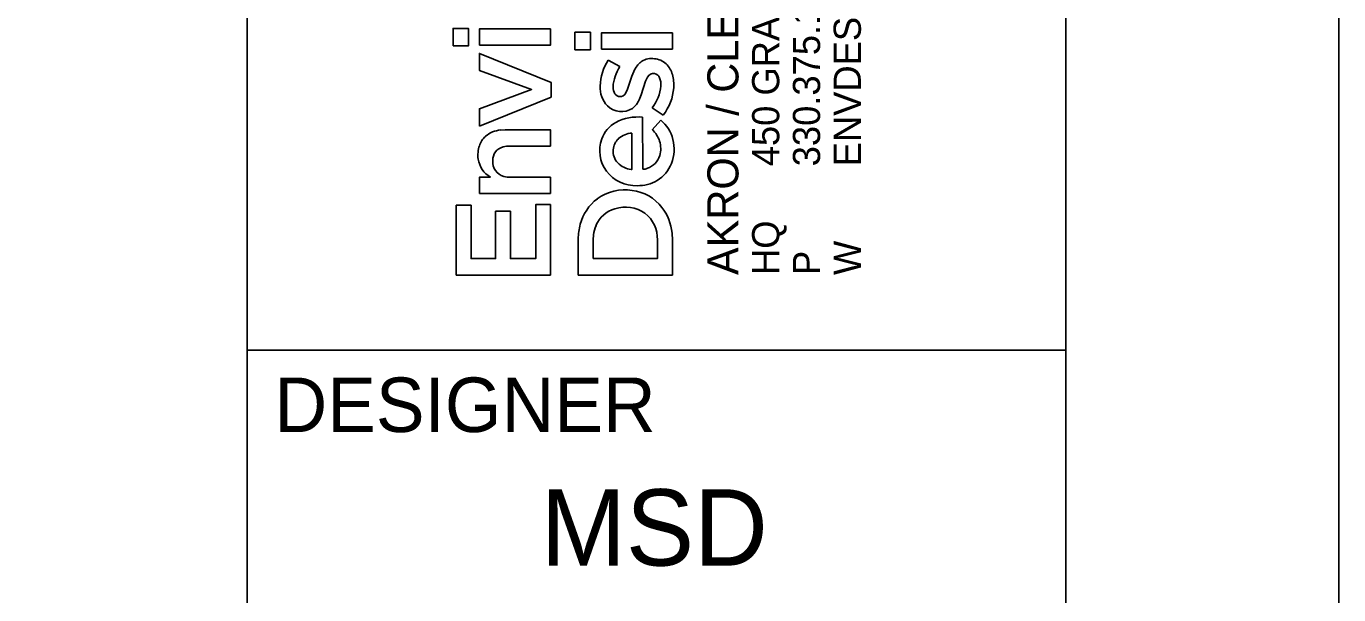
# Model space of a CAD drawing. Extents: x -4.5 to 34, y -0.4 to 22.
# Drawn here: x 31.595 to 34, y 2.552 to 3.594 of the extents above; entities that cross this region are included whole.
import ezdxf

# ---------------------------------------------------------------- set-up
doc = ezdxf.new("R2010")
doc.units = 0
for name, color, linetype in [('SH_Border', 7, 'Continuous'), ('SH_Cut_Line', 7, 'Continuous'), ('SH_Data', 7, 'Continuous')]:
    doc.layers.add(name, color=color, linetype=linetype)

msp = doc.modelspace()

# ---------------------------------------------------------------- linework, layer by layer
at = {"layer": 'SH_Border'}
for p, q in [((32, 0.5), (32, 21.5)), ((32, 3), (33.5, 3))]:
    msp.add_line(p, q, dxfattribs=at)
msp.add_lwpolyline([(1.5, 21.5), (33.5, 21.5), (33.5, 0.5), (1.5, 0.5)], close=True, dxfattribs=at)
at = {"layer": 'SH_Cut_Line'}
msp.add_lwpolyline([(0, 0), (34, 0), (34, 22), (0, 22)], close=True, dxfattribs=at)
at = {"layer": 'SH_Data'}
for p, q in [((32.3771, 3.5582), (32.3771, 3.5903)), ((32.3771, 3.5903), (32.4054, 3.5903)), ((32.4054, 3.5903), (32.4054, 3.5582)), ((32.4254, 3.5594), (32.4254, 3.5893)), ((32.4254, 3.5893), (32.5557, 3.5893)), ((32.5557, 3.5893), (32.5557, 3.5594)), ((32.5557, 3.5594), (32.4254, 3.5594)), ((32.6005, 3.5511), (32.6005, 3.5832)), ((32.6005, 3.5832), (32.6289, 3.5832)), ((32.6289, 3.5832), (32.6289, 3.5511)), ((32.6489, 3.5523), (32.6489, 3.5822)), ((32.6489, 3.5822), (32.7792, 3.5822)), ((32.7792, 3.5822), (32.7792, 3.5523)), ((32.4054, 3.5582), (32.3771, 3.5582)), ((32.4254, 3.5133), (32.4254, 3.5446)), ((32.4254, 3.5446), (32.5567, 3.4913)), ((32.6289, 3.5511), (32.6005, 3.5511)), ((32.7792, 3.5523), (32.6489, 3.5523)), ((32.5212, 3.478), (32.4254, 3.5133)), ((32.6615, 3.5321), (32.6827, 3.5203)), ((32.7048, 3.5026), (32.7104, 3.5153)), ((32.5567, 3.4913), (32.5567, 3.4644)), ((32.6967, 3.4787), (32.7048, 3.5026)), ((32.7298, 3.4933), (32.7221, 3.4688)), ((32.7334, 3.501), (32.7298, 3.4933)), ((32.4254, 3.4429), (32.5212, 3.478)), ((32.5567, 3.4644), (32.4254, 3.4109)), ((32.693, 3.4712), (32.6967, 3.4787)), ((32.7221, 3.4688), (32.7182, 3.4592)), ((32.4254, 3.4109), (32.4254, 3.4429)), ((32.7621, 3.4314), (32.742, 3.4447)), ((32.7245, 3.4275), (32.7246, 3.3319)), ((32.7423, 3.4046), (32.7577, 3.422)), ((32.4644, 3.404), (32.4729, 3.4044)), ((32.4729, 3.4044), (32.5557, 3.4044)), ((32.5557, 3.4044), (32.5557, 3.3746)), ((32.7049, 3.3318), (32.7049, 3.3983)), ((32.5557, 3.3746), (32.4814, 3.3746)), ((32.7036, 3.3317), (32.7049, 3.3318)), ((32.4254, 3.2875), (32.4254, 3.3173)), ((32.4254, 3.3173), (32.4455, 3.3173)), ((32.4822, 3.3173), (32.5557, 3.3173)), ((32.5557, 3.3173), (32.5557, 3.2876)), ((32.5557, 3.2876), (32.4254, 3.2875)), ((32.383, 3.1379), (32.383, 3.266)), ((32.383, 3.266), (32.4101, 3.266)), ((32.4101, 3.266), (32.4101, 3.1683)), ((32.455, 3.1683), (32.455, 3.2549)), ((32.455, 3.2549), (32.4822, 3.2549)), ((32.4822, 3.2549), (32.4822, 3.1683)), ((32.5286, 3.1683), (32.5286, 3.2672)), ((32.5286, 3.2672), (32.5557, 3.2672)), ((32.5557, 3.2672), (32.5557, 3.1379)), ((32.6064, 3.138), (32.6064, 3.204)), ((32.6347, 3.2118), (32.6341, 3.2023)), ((32.6341, 3.2023), (32.6341, 3.1684)), ((32.7515, 3.1683), (32.7515, 3.2024)), ((32.7785, 3.215), (32.7792, 3.2021)), ((32.7792, 3.2021), (32.7792, 3.138)), ((32.4101, 3.1683), (32.455, 3.1683)), ((32.4822, 3.1683), (32.5286, 3.1683)), ((32.6341, 3.1684), (32.7515, 3.1683)), ((32.5557, 3.1379), (32.383, 3.1379)), ((32.7792, 3.138), (32.6064, 3.138))]:
    msp.add_line(p, q, dxfattribs=at)
for points in [[(32.3771, 3.5582), (32.3771, 3.5903), (32.4054, 3.5903), (32.4054, 3.5582)], [(32.4254, 3.5594), (32.4254, 3.5893), (32.5557, 3.5893), (32.5557, 3.5594)], [(32.6005, 3.5511), (32.6005, 3.5832), (32.6289, 3.5832), (32.6289, 3.5511)], [(32.6489, 3.5523), (32.6489, 3.5822), (32.7792, 3.5822), (32.7792, 3.5523)], [(32.4254, 3.4109), (32.4254, 3.4429), (32.5212, 3.478), (32.4254, 3.5133), (32.4254, 3.5446), (32.5567, 3.4913), (32.5567, 3.4644)], [(32.383, 3.1379), (32.383, 3.266), (32.4101, 3.266), (32.4101, 3.1683), (32.455, 3.1683), (32.455, 3.2549), (32.4822, 3.2549), (32.4822, 3.1683), (32.5286, 3.1683), (32.5286, 3.2672), (32.5557, 3.2672), (32.5557, 3.1379)]]:
    msp.add_lwpolyline(points, close=True, dxfattribs=at)
for points in [[(32.6615, 3.5321), (32.6827, 3.5203)], [(32.693, 3.4712), (32.6967, 3.4787), (32.7048, 3.5026), (32.7104, 3.5153)], [(32.7334, 3.501), (32.7298, 3.4933), (32.7221, 3.4688), (32.7182, 3.4592)], [(32.7621, 3.4314), (32.742, 3.4447)], [(32.7245, 3.4275), (32.7246, 3.3319)], [(32.7423, 3.4046), (32.7577, 3.422)], [(32.4644, 3.404), (32.4729, 3.4044), (32.5557, 3.4044), (32.5557, 3.3746), (32.4814, 3.3746)], [(32.7036, 3.3317), (32.7049, 3.3318), (32.7049, 3.3983)], [(32.4254, 3.2875), (32.4254, 3.3173), (32.4455, 3.3173)], [(32.4822, 3.3173), (32.5557, 3.3173), (32.5557, 3.2876), (32.4254, 3.2875)], [(32.7785, 3.215), (32.7792, 3.2021), (32.7792, 3.138), (32.6064, 3.138)], [(32.6064, 3.138), (32.6064, 3.204)], [(32.6347, 3.2118), (32.6341, 3.2023), (32.6341, 3.1684), (32.7515, 3.1683), (32.7515, 3.2024)]]:
    msp.add_lwpolyline(points, dxfattribs=at)
for centre, radius, start, end in [((32.7406, 3.5026), 0.0326, 80.1719, 122.5197), ((32.7406, 3.5026), 0.0326, 80.1719, 122.5197), ((32.7364, 3.4826), 0.0897, 146.531, 178.7571), ((32.7364, 3.4826), 0.0897, 146.531, 178.7571), ((32.7452, 3.4789), 0.0749, 146.5112, 176.9101), ((32.7452, 3.4789), 0.0749, 146.5112, 176.9101), ((32.7466, 3.4971), 0.0405, 125.5118, 153.4159), ((32.7466, 3.4971), 0.0405, 125.5118, 153.4159), ((32.7428, 3.4982), 0.0367, 47.7934, 84.6892), ((32.7428, 3.4982), 0.0367, 47.7934, 84.6892), ((32.7379, 3.4946), 0.0427, 14.9966, 46.2063), ((32.7379, 3.4946), 0.0427, 14.9966, 46.2063), ((32.7438, 3.4963), 0.0114, 76.6609, 155.7053), ((32.7438, 3.4963), 0.0114, 76.6609, 155.7053), ((32.744, 3.4951), 0.0126, 21.5098, 78.5262), ((32.744, 3.4951), 0.0126, 21.5098, 78.5262), ((32.7259, 3.4877), 0.0321, 354.5726, 22.068), ((32.7259, 3.4877), 0.0321, 354.5726, 22.068), ((32.7104, 3.4867), 0.0712, 355.8306, 15.3914), ((32.7104, 3.4867), 0.0712, 355.8306, 15.3914), ((32.6967, 3.4824), 0.0501, 177.5366, 222.7932), ((32.6967, 3.4824), 0.0501, 177.5366, 222.7932), ((32.6931, 3.4823), 0.0228, 178.4747, 211.0868), ((32.6931, 3.4823), 0.0228, 178.4747, 211.0868), ((32.6833, 3.4767), 0.0115, 212.2368, 268.3777), ((32.6833, 3.4767), 0.0115, 212.2368, 268.3777), ((32.6834, 3.4759), 0.0107, 267.716, 333.7337), ((32.6834, 3.4759), 0.0107, 267.716, 333.7337), ((32.6825, 3.4915), 0.0757, 321.811, 354.7969), ((32.6825, 3.4915), 0.0757, 321.811, 354.7969), ((32.6895, 3.4882), 0.0922, 321.9777, 355.8738), ((32.6895, 3.4882), 0.0922, 321.9777, 355.8738), ((32.686, 3.4753), 0.0375, 225.9854, 302.4797), ((32.686, 3.4753), 0.0375, 225.9854, 302.4797), ((32.681, 3.4758), 0.0408, 308.0877, 335.9874), ((32.681, 3.4758), 0.0408, 308.0877, 335.9874), ((32.7024, 3.3691), 0.0558, 118.8308, 160.6244), ((32.7024, 3.3691), 0.0558, 118.8308, 160.6244), ((32.7152, 3.3441), 0.0838, 83.615, 118.2876), ((32.7152, 3.3441), 0.0838, 83.615, 118.2876), ((32.7174, 3.3717), 0.0644, 13.5336, 51.3615), ((32.7174, 3.3717), 0.0644, 13.5336, 51.3615), ((32.4635, 3.3626), 0.0402, 132.2219, 161.6818), ((32.4635, 3.3626), 0.0402, 132.2219, 161.6818), ((32.4687, 3.3543), 0.0499, 94.9696, 130.2225), ((32.4687, 3.3543), 0.0499, 94.9696, 130.2225), ((32.7079, 3.3561), 0.0424, 94.008, 130.8817), ((32.7079, 3.3561), 0.0424, 94.008, 130.8817), ((32.7038, 3.3656), 0.0549, 19.0357, 45.4406), ((32.7038, 3.3656), 0.0549, 19.0357, 45.4406), ((32.4787, 3.3582), 0.056, 162.2736, 187.7919), ((32.4787, 3.3582), 0.056, 162.2736, 187.7919), ((32.4748, 3.3487), 0.025, 103.6865, 182.2187), ((32.4748, 3.3487), 0.025, 103.6865, 182.2187), ((32.4811, 3.3286), 0.046, 89.6049, 105.3284), ((32.4811, 3.3286), 0.046, 89.6049, 105.3284), ((32.7104, 3.3661), 0.0644, 160.5201, 215.7831), ((32.7104, 3.3661), 0.0644, 160.5201, 215.7831), ((32.7017, 3.365), 0.0311, 175.0013, 223.283), ((32.7017, 3.365), 0.0311, 175.0013, 223.283), ((32.7005, 3.3663), 0.0298, 132.9851, 177.179), ((32.7005, 3.3663), 0.0298, 132.9851, 177.179), ((32.7107, 3.3697), 0.047, 344.6059, 17.007), ((32.7107, 3.3697), 0.047, 344.6059, 17.007), ((32.7064, 3.3692), 0.0758, 339.3542, 13.3785), ((32.7064, 3.3692), 0.0758, 339.3542, 13.3785), ((32.4703, 3.358), 0.0476, 188.962, 238.7037), ((32.4703, 3.358), 0.0476, 188.962, 238.7037), ((32.4773, 3.3456), 0.0276, 175.5854, 255.1439), ((32.4773, 3.3456), 0.0276, 175.5854, 255.1439), ((32.7089, 3.3736), 0.0423, 225.0619, 262.7974), ((32.7089, 3.3736), 0.0423, 225.0619, 262.7974), ((32.7224, 3.3671), 0.035, 288.0077, 343.5508), ((32.7224, 3.3671), 0.035, 288.0077, 343.5508), ((32.4818, 3.3595), 0.0422, 254.0916, 270.5284), ((32.4818, 3.3595), 0.0422, 254.0916, 270.5284), ((32.7125, 3.3705), 0.0687, 217.7452, 271.6543), ((32.7125, 3.3705), 0.0687, 217.7452, 271.6543), ((32.7247, 3.3522), 0.0202, 269.7003, 294.8711), ((32.7247, 3.3522), 0.0202, 269.7003, 294.8711), ((32.7189, 3.3652), 0.0626, 300.9427, 338.7323), ((32.7189, 3.3652), 0.0626, 300.9427, 338.7323), ((32.7155, 3.3724), 0.0706, 269.2048, 300.3341), ((32.7155, 3.3724), 0.0706, 269.2048, 300.3341), ((32.6939, 3.2089), 0.0865, 127.2362, 165.148), ((32.6939, 3.2089), 0.0865, 127.2362, 165.148), ((32.6923, 3.2079), 0.0864, 81.194, 125.9984), ((32.6923, 3.2079), 0.0864, 81.194, 125.9984), ((32.6946, 3.2113), 0.0827, 37.8521, 82.402), ((32.6946, 3.2113), 0.0827, 37.8521, 82.402), ((32.6889, 3.2078), 0.054, 106.1881, 157.3861), ((32.6889, 3.2078), 0.054, 106.1881, 157.3861), ((32.6928, 3.1986), 0.0639, 55.6727, 107.2093), ((32.6928, 3.1986), 0.0639, 55.6727, 107.2093), ((32.6929, 3.205), 0.0587, 357.4662, 52.2665), ((32.6929, 3.205), 0.0587, 357.4662, 52.2665), ((32.6859, 3.2057), 0.0931, 5.7333, 37.304), ((32.6859, 3.2057), 0.0931, 5.7333, 37.304), ((32.7143, 3.2028), 0.1078, 164.7861, 179.3704), ((32.7143, 3.2028), 0.1078, 164.7861, 179.3704), ((32.6983, 3.2039), 0.0641, 157.3571, 172.9275), ((32.6983, 3.2039), 0.0641, 157.3571, 172.9275)]:
    msp.add_arc(centre, radius, start, end, dxfattribs=at)

# ---------------------------------------------------------------- texts
for s, height, p in [('450 GRANT ST., AKRON, OH  44311', 0.049846, (32.9749, 3.3374)), ('AKRON / CLEVELAND / COLUMBUS', 0.056969, (32.9001, 3.138)), ('ENVDESIGNGROUP.COM', 0.049846, (33.1244, 3.3374)), ('330.375.1390', 0.049846, (33.0497, 3.3374)), ('HQ ', 0.04985, (32.9749, 3.138)), ('W', 0.0498, (33.1244, 3.138)), ('P', 0.0498, (33.0497, 3.138))]:
    msp.add_text(s, height=height, rotation=90, dxfattribs=at).set_placement(p)
for s, height, p in [('DESIGNER', 0.1, (32.05, 2.85)), ('MSD', 0.14, (32.5379, 2.605))]:
    msp.add_text(s, height=height, dxfattribs=at).set_placement(p)

doc.saveas('drawing.dxf')
